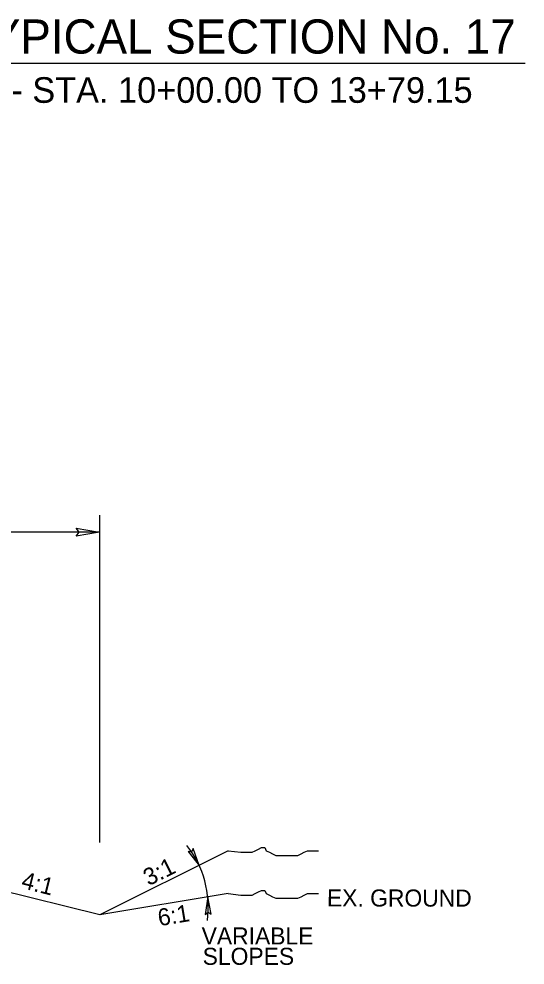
# Model space of a CAD drawing. Extents: x 2320980 to 2456309, y 595047 to 606177.
# Drawn here: x 2455866 to 2455905.4, y 595699.2 to 595772.8 of the extents above; entities that cross this region are included whole.
import ezdxf

# ---------------------------------------------------------------- set-up
doc = ezdxf.new("R2010")
doc.units = 0
for name, color, linetype in [('Old_Level_1', 7, 'Continuous'), ('Old_Level_11', 7, 'Continuous'), ('Old_Level_2', 7, 'Continuous'), ('Old_Level_3', 7, 'Continuous'), ('Prop Dimension', 7, 'Continuous'), ('Typical Hinge Slope Arterial CELL', 7, 'Continuous'), ('Typical Terminator CELL', 7, 'Continuous')]:
    doc.layers.add(name, color=color, linetype=linetype)

msp = doc.modelspace()

# ---------------------------------------------------------------- linework, layer by layer
at = {"layer": 'Old_Level_11'}
msp.add_lwpolyline([(2455870.479, 595733.194), (2455872.279, 595732.884), (2455870.469, 595732.564), (2455870.699, 595732.884)], close=True, dxfattribs=at)
at = {"layer": 'Old_Level_3'}
msp.add_line((2455860.483, 595769.405), (2455905.403, 595769.405), dxfattribs=at)
at = {"layer": 'Prop Dimension'}
for p, q in [((2455872.311, 595708.724), (2455872.311, 595734.214)), ((2455872.279, 595732.884), (2455857.279, 595732.884))]:
    msp.add_line(p, q, dxfattribs=at)
at = {"layer": 'Typical Hinge Slope Arterial CELL'}
for p, q in [((2455882.311, 595708.089), (2455872.311, 595703.089)), ((2455872.311, 595703.089), (2455857.311, 595706.839)), ((2455882.311, 595704.756), (2455872.311, 595703.089))]:
    msp.add_line(p, q, dxfattribs=at)
for points in [[(2455882.311, 595708.089), (2455883.296, 595707.966), (2455883.543, 595707.966), (2455883.913, 595707.966), (2455884.159, 595707.966), (2455884.405, 595708.089), (2455884.652, 595708.212), (2455884.898, 595708.336), (2455885.144, 595708.336), (2455885.268, 595708.089), (2455885.515, 595707.966), (2455885.761, 595707.842), (2455886.007, 595707.72), (2455886.254, 595707.72), (2455886.5, 595707.72), (2455886.746, 595707.72), (2455886.993, 595707.72), (2455887.239, 595707.72), (2455887.485, 595707.72), (2455887.732, 595707.72), (2455887.978, 595707.842), (2455888.225, 595707.966), (2455888.471, 595708.089), (2455888.841, 595708.089), (2455889.087, 595708.089), (2455889.334, 595708.089)], [(2455882.311, 595704.756), (2455883.296, 595704.633), (2455883.543, 595704.633), (2455883.913, 595704.633), (2455884.159, 595704.633), (2455884.405, 595704.756), (2455884.652, 595704.879), (2455884.898, 595705.003), (2455885.144, 595705.003), (2455885.268, 595704.756), (2455885.515, 595704.633), (2455885.761, 595704.509), (2455886.007, 595704.387), (2455886.254, 595704.387), (2455886.5, 595704.387), (2455886.746, 595704.387), (2455886.993, 595704.387), (2455887.239, 595704.387), (2455887.485, 595704.387), (2455887.732, 595704.387), (2455887.978, 595704.509), (2455888.225, 595704.633), (2455888.471, 595704.756), (2455888.841, 595704.756), (2455889.087, 595704.756), (2455889.334, 595704.756)]]:
    msp.add_lwpolyline(points, dxfattribs=at)
msp.add_arc((2455873.017, 595703.706), 7.737, 352.25254, 38.26613, dxfattribs=at)
at = {"layer": 'Typical Terminator CELL'}
for points in [[(2455879.178, 595708.018), (2455880.039, 595706.953), (2455879.587, 595708.255), (2455879.461, 595707.987)], [(2455880.987, 595703.147), (2455880.714, 595704.489), (2455880.515, 595703.125), (2455880.75, 595703.305)]]:
    msp.add_lwpolyline(points, close=True, dxfattribs=at)

# ---------------------------------------------------------------- texts
at = {"layer": 'Old_Level_1'}
msp.add_text('EX. GROUND', height=1.33, rotation=359.91026, dxfattribs=at).set_placement((2455889.987, 595703.753))
at = {"layer": 'Old_Level_2'}
for s, height, p in [('TYPICAL SECTION No. 17', 2.66, (2455861.587, 595770.138)), ('-Y19- STA. 10+00.00 TO 13+79.15', 1.995, (2455859.798, 595766.306))]:
    msp.add_text(s, height=height, dxfattribs=at).set_placement(p)
at = {"layer": 'Typical Hinge Slope Arterial CELL'}
for s, rotation, p in [('3:1', 26.56505, (2455876.114, 595705.319)), ('4:1', 345.96376, (2455866.135, 595705.198)), ('6:1', 9.46348, (2455876.943, 595702.212))]:
    msp.add_text(s, height=1.33, rotation=rotation, dxfattribs=at).set_placement(p)
for s, p in [('VARIABLE ', (2455880.238, 595700.792)), ('SLOPES', (2455880.317, 595699.208))]:
    msp.add_text(s, height=1.33, dxfattribs=at).set_placement(p)

doc.saveas('drawing.dxf')
